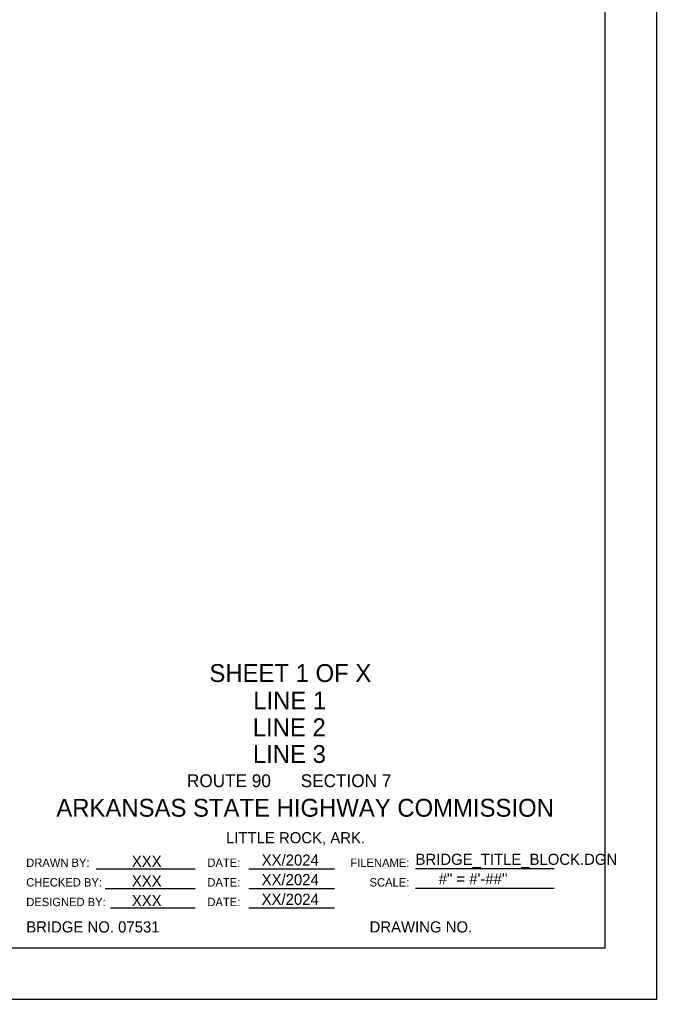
# Model space of a CAD drawing. Extents: x 16 to 1228740, y 11 to 152440.
# Drawn here: x 17.895 to 18.49, y 10.709 to 11.626 of the extents above; entities that cross this region are included whole.
import ezdxf

# ---------------------------------------------------------------- set-up
doc = ezdxf.new("R2010")
doc.units = 0
for name, color, linetype in [('B_Copy In', 7, 'Continuous'), ('B_Text', 7, 'Continuous'), ('R_Border', 7, 'Continuous'), ('R_No Plot', 7, 'Continuous')]:
    doc.layers.add(name, color=color, linetype=linetype)

msp = doc.modelspace()

# ---------------------------------------------------------------- linework, layer by layer
at = {"layer": 'B_Text'}
for p, q in [((17.96633, 10.83175), (18.05897, 10.83175)), ((18.109, 10.83175), (18.18935, 10.83175)), ((18.26484, 10.83184), (18.39463, 10.83184)), ((17.97479, 10.81339), (18.05897, 10.81339)), ((18.109, 10.81339), (18.18935, 10.81339)), ((18.26484, 10.81348), (18.39463, 10.81348)), ((17.97987, 10.79503), (18.05897, 10.79503)), ((18.109, 10.79503), (18.18935, 10.79503))]:
    msp.add_line(p, q, dxfattribs=at)
at = {"layer": 'R_Border'}
for q in [(18.44221, 12.49475), (15.78327, 10.75755)]:
    msp.add_line((18.44221, 10.75755), q, dxfattribs=at)
at = {"layer": 'R_No Plot'}
msp.add_lwpolyline([(15.65694, 12.54282), (18.49027, 12.54282), (18.49027, 10.70949), (15.65694, 10.70949)], close=True, dxfattribs=at)

# ---------------------------------------------------------------- texts
at = {"layer": 'B_Copy In'}
msp.add_text('SHEET 1 OF X', height=0.0167, rotation=360, dxfattribs=at).set_placement((18.07224, 11.00645))
for s, height, p in [('LINE 1', 0.0167, (18.11321, 10.98081)), ('LINE 2', 0.0167, (18.11279, 10.95576)), ('LINE 3', 0.0167, (18.11293, 10.93071)), ('ROUTE 90', 0.012, (18.05126, 10.90806)), ('SECTION 7', 0.012, (18.15768, 10.90806)), ('XX/2024', 0.010417, (18.1211, 10.83468)), ('BRIDGE_TITLE_BLOCK.DGN', 0.0104, (18.26501, 10.83535)), ('XXX', 0.010417, (17.99969, 10.83346)), ('XX/2024', 0.010417, (18.1211, 10.81632)), ('#" = #\'-##\'\'', 0.0104166, (18.28669, 10.81712)), ('XXX', 0.010417, (17.99969, 10.8151)), ('XX/2024', 0.010417, (18.1211, 10.79796)), ('XXX', 0.010417, (17.99969, 10.79673)), ('BRIDGE NO. 07531', 0.0104167, (17.90093, 10.77209)), ('DRAWING NO.      ', 0.0104167, (18.22203, 10.77209))]:
    msp.add_text(s, height=height, dxfattribs=at).set_placement(p)
at = {"layer": 'B_Text'}
for s, height, p in [('ARKANSAS STATE HIGHWAY COMMISSION', 0.0167, (17.92909, 10.88041)), ('LITTLE ROCK, ARK.', 0.0104167, (18.08778, 10.85556)), ('DRAWN BY:', 0.007812, (17.90093, 10.83346)), ('DATE:', 0.007812, (18.07036, 10.83346)), ('FILENAME:', 0.007812, (18.20409, 10.83346)), ('CHECKED BY:', 0.0078125, (17.90093, 10.8151)), ('DATE:', 0.007812, (18.07036, 10.8151)), ('SCALE:', 0.007812, (18.22203, 10.8151)), ('DESIGNED BY:', 0.0078125, (17.90093, 10.79673)), ('DATE:', 0.007812, (18.07036, 10.79673))]:
    msp.add_text(s, height=height, dxfattribs=at).set_placement(p)

doc.saveas('drawing.dxf')
